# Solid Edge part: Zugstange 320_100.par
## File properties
Username: ahadarics
Dokumentum tartalom típus: 0
Author: ahadarics
Last saved by: ahadarics
Revision: 81
Sűrűség: 0,000 kg/m^3
Pontosság: 0,990
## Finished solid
Body 1: solid body, 9 faces, 15 edges, 8 vertices.
  Faces by surface: cone 4, cylinder 3, plane 2
  Edges by curve: circle 11, line 4
Bounding box of the edges (mm): 25.000 x 25.000 x 262.000, from (-12.5, -12.5, -168.5) to (12.5, 12.5, 93.5).
Cylindrical faces by radius (mm): R12 x2, R12.5 x1
Conical faces (half-angle, radius in mm at the cone's reference point): 30 deg R12.25 x2, 45 deg R11 x2
Planar faces by outward normal: +z 1, -z 1
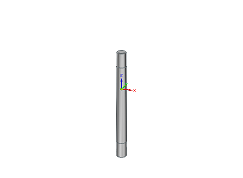
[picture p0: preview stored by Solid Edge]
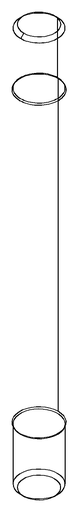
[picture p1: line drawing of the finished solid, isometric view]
